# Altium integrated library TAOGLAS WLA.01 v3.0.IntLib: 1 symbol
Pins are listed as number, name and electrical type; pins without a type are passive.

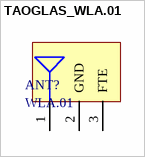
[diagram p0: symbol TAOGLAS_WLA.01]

## TAOGLAS_WLA.01
designator ANT?, comment WLA.01
2400MHz to 2500MHz WLAN/Wi-Fi/Bluetooth; ComponentLibStatus: Created; MFG: Taoglas; Temp_High: +85C; Temp_Low: -40C
footprint TAOGLAS_WLA.01 (2400MHz to 2500MHz WLAN/Wi-Fi/Bluetooth)
pins: 1 RF OUT, 2 GND, 3 FTE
